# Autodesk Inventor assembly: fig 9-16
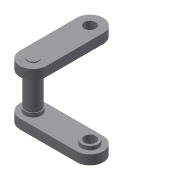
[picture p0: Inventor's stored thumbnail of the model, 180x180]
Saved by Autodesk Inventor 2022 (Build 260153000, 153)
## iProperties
Created: 2002-01
Part Number: fig 9-16
Document SubType Name: Assembly
Designer: ***
Control State: 0
Master: False
Checked Out: False
Shininess: 64.0
Length Units: 11269
Angle Units: 11279
Time Units: 11290
Mass Units: 11283
Length Display Precision: 3
Angle Display Precision: 2
Density: 0.0
Volumn: 0.0
Area: 0.0
PropertySet Name: Model Information
Author: ***
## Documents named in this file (3)
- D:\PROJECTS_2021\Resources\Part Files\c09_Inv_2022_prt\fig 9-16.iam
- D:\PROJECTS_2021\Resources\Part Files\c09_Inv_2022_prt\Part5.ipt
- D:\PROJECTS_2021\Resources\Part Files\c09_Inv_2022_prt\Part6.ipt
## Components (3 placed, 2 different names)
1. Part5:1 — Insert:1, Angle:1
2. Part6:1 — Insert:1, Insert:2
3. Part5:2 — Insert:2, Angle:1
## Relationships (3: Insert 2, Angle 1)
- Insert:1: Part5:1 ↔ Part6:1
- Insert:2: Part6:1 ↔ Part5:2
- Angle:1: Part5:1 ↔ Part5:2
